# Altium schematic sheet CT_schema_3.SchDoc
size 335 x 238 mm
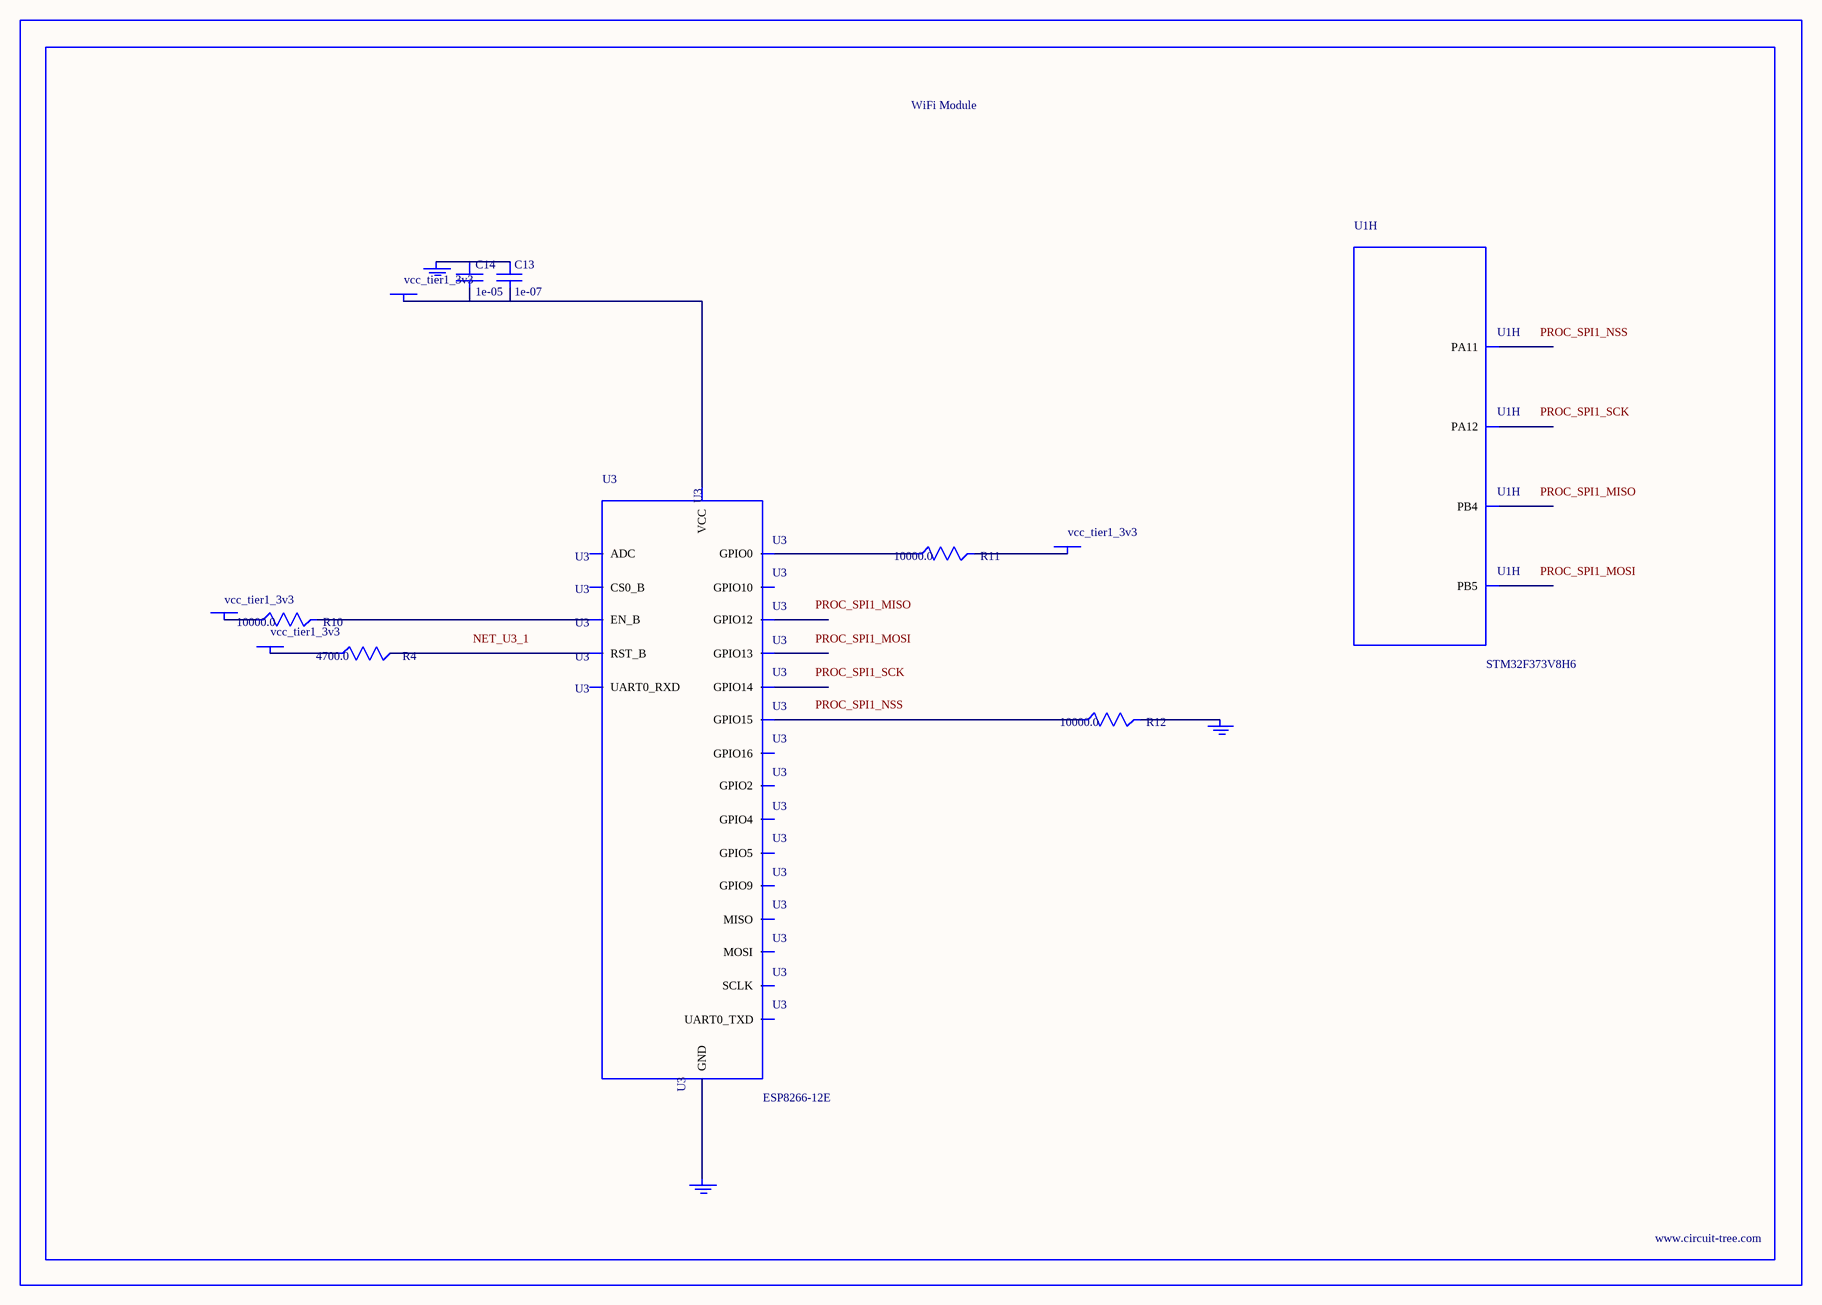
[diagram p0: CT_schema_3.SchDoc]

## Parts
BORDER2  (no value)
C13  1e-07  [C0402]
C14  1e-05  [C0805]
GND_INSTANCE_2_0  (no value)
GND_INSTANCE_2_1  (no value)
GND_INSTANCE_2_2  (no value)
POWER_INSTANCE_2_0  vcc_tier1_3v3
POWER_INSTANCE_2_1  vcc_tier1_3v3
POWER_INSTANCE_2_2  vcc_tier1_3v3
POWER_INSTANCE_2_3  vcc_tier1_3v3
R4  4700.0  [R0603]
R10  10000.0  [R0603]
R11  10000.0  [R0603]
R12  10000.0  [R0603]
U1  STM32F373V8H6  [UFBGA100]  (part H of 9)
U3  ESP8266-12E  [ESP8266-12E]

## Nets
NetC13_1: C13.1 C14.1 GND_INSTANCE_2_0.0(GND)
NetC13_2: C13.2 C14.2 POWER_INSTANCE_2_1.0(PWR) U3.8(VCC)
NetGND_INSTANCE_2_1_0: GND_INSTANCE_2_1.0(GND) R12.2
NetGND_INSTANCE_2_2_0: GND_INSTANCE_2_2.0(GND) U3.15(GND)
NetPOWER_INSTANCE_2_0_0: POWER_INSTANCE_2_0.0(PWR) R10.1
NetPOWER_INSTANCE_2_2_0: POWER_INSTANCE_2_2.0(PWR) R11.2
NetPOWER_INSTANCE_2_3_0: POWER_INSTANCE_2_3.0(PWR) R4.1
NetR4_2: R4.2 U3.1(RST_B)
NetR10_2: R10.2 U3.3(EN_B)
NetR11_1: R11.1 U3.18(GPIO0)
NetR12_1: R12.1 U3.16(GPIO15)

Not connected (* = marked no-connect by the designer): U1 A7(PB4) A12(PA12) B12(PA11) C5(PB5); U3 2(ADC) 4(GPIO16) 5(GPIO14) 6(GPIO12) 7(GPIO13) 9(CS0_B) 10(MISO) 11(GPIO9) 12(GPIO10) 13(MOSI) 14(SCLK) 17(GPIO2) 19(GPIO4) 20(GPIO5) 21(UART0_RXD) 22(UART0_TXD)

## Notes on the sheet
- Labels drawn without touching a wire or pin: NET_U3_1, PROC_SPI1_MISO, PROC_SPI1_MOSI, PROC_SPI1_NSS, PROC_SPI1_SCK

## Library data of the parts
BORDER2 = BORDER_PAGE2
C13 = C0402C104K3RACTU
C14 = C0805C106K8RACTU
GND_INSTANCE_2_0-GND_INSTANCE_2_2 = GND
POWER_INSTANCE_2_0-POWER_INSTANCE_2_3 = PWR
R4 = RC0603JR-074K7L
R10-R12 = RC0603JR-0710KL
